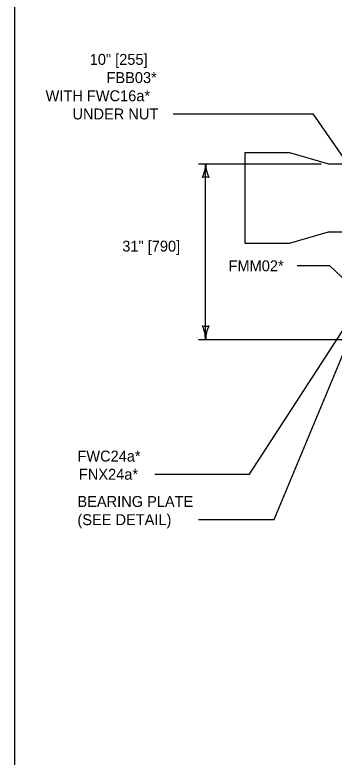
# Model space of a CAD drawing. Extents: x 49991.4 to 50021, y 49987.6 to 50011.4.
# Drawn here: x 49999.384 to 50001.141, y 49992.759 to 49996.841 of the extents above; entities that cross this region are included whole.
import ezdxf

# ---------------------------------------------------------------- set-up
doc = ezdxf.new("R2010")
doc.units = 0
for name, color, linetype in [('Level 1', 7, 'Continuous'), ('Level 2', 7, 'Continuous'), ('Level 3', 7, 'Continuous')]:
    doc.layers.add(name, color=color, linetype=linetype)

msp = doc.modelspace()

# ---------------------------------------------------------------- linework, layer by layer
at = {"layer": 'Level 1'}
for p, q in [((50000.6499, 49996.0848), (50000.6499, 49995.5847)), ((50000.6499, 49996.0848), (50000.8945, 49996.0848)), ((50000.8945, 49996.0848), (50001.1097, 49996.0223)), ((50001.1097, 49996.0223), (50006.4116, 49996.0223)), ((50000.8945, 49995.5847), (50001.1097, 49995.6473)), ((50001.1097, 49995.6473), (50006.4116, 49995.6473)), ((50000.6499, 49995.5847), (50000.8945, 49995.5847)), ((50000.3936, 49995.0551), (50001.2515, 49995.0551))]:
    msp.add_line(p, q, dxfattribs=at)
msp.add_lwpolyline([(49999.3835, 49998.9992), (50016.7501, 49998.9992), (50016.7501, 49987.7988), (49999.3835, 49987.7988)], close=True, dxfattribs=at)
at = {"layer": 'Level 3'}
for p, q in [((50000.2546, 49996.2962), (50001.0256, 49996.2962)), ((50001.3452, 49995.8348), (50001.0256, 49996.2962)), ((50000.3936, 49996.0223), (50001.0697, 49996.0223)), ((50000.4336, 49995.0551), (50000.4336, 49996.0223)), ((50001.1178, 49995.4611), (50000.9373, 49995.4611)), ((50001.1178, 49995.4611), (50001.389, 49995.2033)), ((50000.6742, 49994.3147), (50001.209, 49995.1371)), ((50000.8108, 49994.0651), (50001.2318, 49995.0782)), ((50000.1534, 49994.3147), (50000.6742, 49994.3147)), ((50000.3943, 49994.0651), (50000.8108, 49994.0651))]:
    msp.add_line(p, q, dxfattribs=at)
for centre, radius, start, end in [((50000.2115, 49996.0315), 0.2223, 337.456, 357.6395), ((50000.6663, 49996.0338), 0.233, 182.8273, 202.0772), ((50000.4336, 49995.8941), 0.0548, 72.1388, 107.8612), ((50000.4336, 49995.1834), 0.0548, 252.1388, 287.8612), ((50000.2009, 49995.0436), 0.233, 2.8273, 22.0772), ((50000.6557, 49995.046), 0.2223, 157.456, 177.6395)]:
    msp.add_arc(centre, radius, start, end, dxfattribs=at)

# ---------------------------------------------------------------- texts
at = {"layer": 'Level 2'}
for s, p in [('10" [255] ', (49999.7957, 49996.5662)), ('FBB03* ', (49999.8881, 49996.4662)), ('WITH FWC16a*', (49999.5528, 49996.3662)), ('UNDER NUT', (49999.7006, 49996.2662)), ('31" [790]', (49999.9748, 49995.5392)), ('FMM02*', (50000.5597, 49995.4311)), ('FWC24a*', (49999.728, 49994.3847)), ('FNX24a*', (49999.7362, 49994.2847)), ('BEARING PLATE', (49999.728, 49994.1351)), ('(SEE DETAIL)', (49999.728, 49994.0351))]:
    msp.add_text(s, height=0.06, dxfattribs=at).set_placement(p)

doc.saveas('drawing.dxf')
